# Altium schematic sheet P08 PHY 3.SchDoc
size 420 x 297 mm
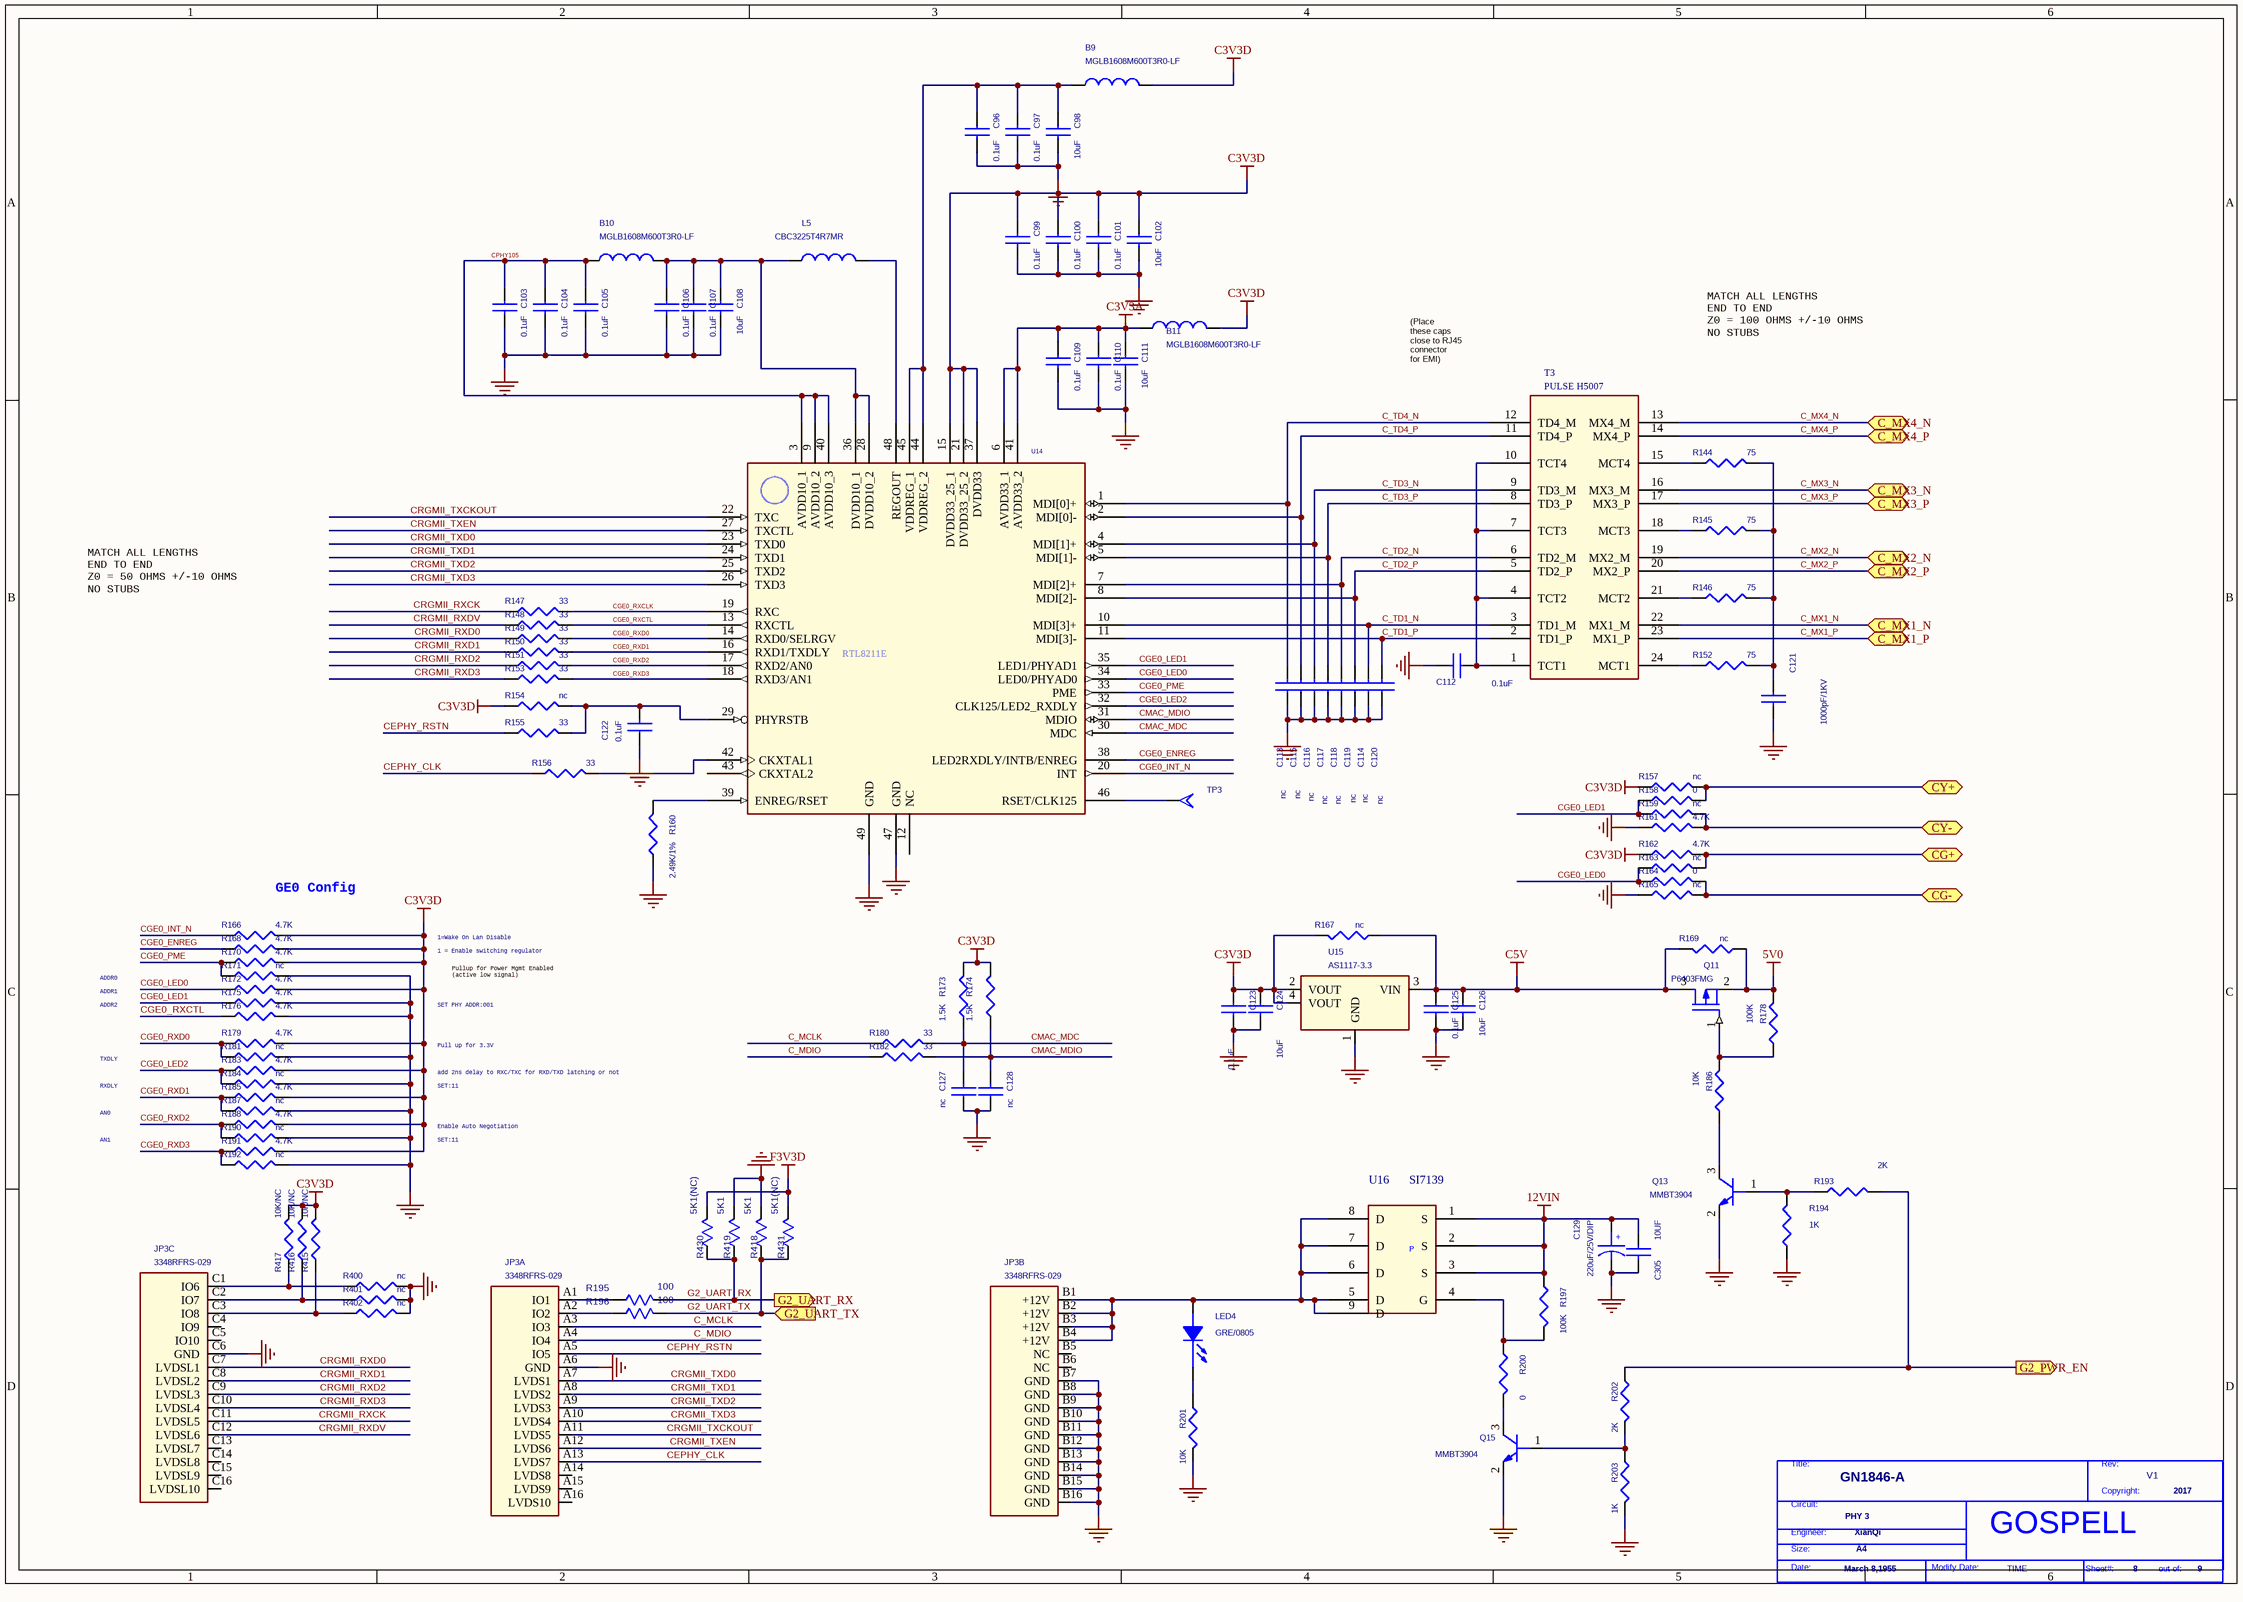
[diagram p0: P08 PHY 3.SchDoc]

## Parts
*  Doc: PHY 3  Page Count: 9  Page Number: 8  Page Create Date: March 8,1955  Page Size: A4  RevCode: V1  Title: GN1846-A  Copyright: 2017  Engineer: XianQi  Page Modify Date: TIME  (hidden comment: GOSPELL)  (graphical)
B9  MGLB1608M600T3R0-LF  [L0603]
B10  MGLB1608M600T3R0-LF  [L0603]
B11  MGLB1608M600T3R0-LF  [L0603]
C96  0.1uF  [0402C]
C97  0.1uF  [0402C]
C98  10uF  [C0603]
C99  0.1uF  [0402C]
C100  0.1uF  [0402C]
C101  0.1uF  [0402C]
C102  10uF  [C0603]
C103  0.1uF  [0402C]
C104  0.1uF  [0402C]
C105  0.1uF  [0402C]
C106  0.1uF  [0402C]
C107  0.1uF  [0402C]
C108  10uF  [C0603]
C109  0.1uF  [0402C]
C110  0.1uF  [0402C]
C111  10uF  [C0603]
C112  0.1uF  [0402C]
C113  nc  [0402C]
C114  nc  [0402C]
C115  nc  [0402C]
C116  nc  [0402C]
C117  nc  [0402C]
C118  nc  [0402C]
C119  nc  [0402C]
C120  nc  [0402C]
C121  1000pF/1KV  [C1206]
C122  0.1uF  [0402C]
C123  0.1uF  [0402C]
C124  10uF  [C0603]
C125  0.1uF  [0402C]
C126  10uF  [C0603]
C127  nc  [0402C]
C128  nc  [0402C]
C129  220uF/25V/DIP  [CE8X3.5]
C305  10UF  [C1206]
JP3  3348RFRS-029  [3348RFRS-029]  (parts A,B,C of 3)
L5  CBC3225T4R7MR  [FB0805]
LED4  GRE/0805  [LED0805]
Q11  P6403FMG  [SOT23]
Q13  MMBT3904  [SOT23]
Q15  MMBT3904  [SOT23]
R144  75  [0402R]
R145  75  [0402R]
R146  75  [0402R]
R147  33  [0402R]
R148  33  [0402R]
R149  33  [0402R]
R150  33  [0402R]
R151  33  [0402R]
R152  75  [0402R]
R153  33  [0402R]
R154  nc  [0402R]
R155  33  [0402R]
R156  33  [0402R]
R157  nc  [0402R]
R158  0  [0402R]
R159  nc  [0402R]
R160  2.49K/1%  [0402R]
R161  4.7K  [0402R]
R162  4.7K  [0402R]
R163  nc  [0402R]
R164  0  [0402R]
R165  nc  [0402R]
R166  4.7K  [0402R]
R167  nc  [R0603]
R168  4.7K  [0402R]
R169  nc  [R0603]
R170  4.7K  [0402R]
R171  nc  [0402R]
R172  4.7K  [0402R]
R173  1.5K  [0402R]
R174  1.5K  [0402R]
R175  4.7K  [0402R]
R176  4.7K  [0402R]
R178  100K  [0402R]
R179  4.7K  [0402R]
R180  33  [0402R]
R181  nc  [0402R]
R182  33  [0402R]
R183  4.7K  [0402R]
R184  nc  [0402R]
R185  4.7K  [0402R]
R186  10K  [0402R]
R187  nc  [0402R]
R188  4.7K  [0402R]
R190  nc  [0402R]
R191  4.7K  [0402R]
R192  nc  [0402R]
R193  2K  [0402R]
R194  1K  [0402R]
R195  100  [0402R]
R196  100  [0402R]
R197  100K  [R0603]
R200  0  [0402R]
R201  10K  [0402R]
R202  2K  [0402R]
R203  1K  [0402R]
R400  nc  [0402R]
R401  nc  [0402R]
R402  nc  [0402R]
R415  10K/NC  [0402R]
R416  10K/NC  [0402R]
R417  10K/NC  [0402R]
R418  5K1  [0402R]
R419  5K1  [0402R]
R430  5K1(NC)  [0402R]
R431  5K1(NC)  [0402R]
T3  PULSE H5007  [H5007-H]
TP3  T POINT A  [TP_G]  (value not drawn)
U14  RTL8211D  [QFN-48P-RTL8211]  (value not drawn)
U15  AS1117-3.3  [SOT223]
U16  SI7139  [PowerPAKSO8]

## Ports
C_MX1_N (bidir), C_MX1_P (bidir), C_MX2_N (bidir), C_MX2_P (bidir), C_MX3_N (bidir), C_MX3_P (bidir), C_MX4_N (bidir), C_MX4_P (bidir), CG+ (bidir), CG- (bidir), CY+ (bidir), CY- (bidir), G2_PWR_EN (out), G2_UART_RX (out), G2_UART_TX (in)

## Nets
5V0: Q11.2(SOURCE) R169.2 R178.1
12VIN: C129.1 C305.1 R197.2 U16.1(S) U16.2(S) U16.3(S)
C3V3A: B11.1 C109.1 C110.1 C111.1 U14.6(AVDD33_1) U14.41(AVDD33_2)
C3V3D: B9.2 B11.2 C99.1 C100.1 C101.1 C102.1 C123.1 C124.1 R154.1 R157.1 R162.1 R166.2 R167.1 R168.2 R170.2 R172.2 R173.2 R174.2 R179.2 R183.2 R185.2 R188.2 R191.2 R415.2 R416.2 R417.2 U14.15(DVDD33_25_1) U14.21(DVDD33_25_2) U14.37(DVDD33) U15.2(VOUT) U15.4(VOUT)
C5V: C125.1 C126.1 Q11.3(DRAIN) R167.2 R169.1 U15.3(VIN)
F3V3D: R430.2(B) R431.2(B)
GND: C96.2 C97.2 C98.2 C99.2 C100.2 C101.2 C102.2 C103.2 C104.2 C105.2 C106.2 C107.2 C108.2 C109.2 C110.2 C111.2 C112.2 C113.1 C114.1 C115.1 C116.1 C117.1 C118.1 C119.1 C120.1 C121.2 C122.1 C123.2 C124.2 C125.2 C126.2 C127.1 C128.1 C129.2 C305.2 JP3.A6(GND) JP3.B7(GND) JP3.B8(GND) JP3.B9(GND) JP3.B10(GND) JP3.B11(GND) JP3.B12(GND) JP3.B13(GND) JP3.B14(GND) JP3.B15(GND) JP3.B16(GND) JP3.C6(GND) Q13.2(EMITTER) Q15.2(EMITTER) R160.1 R161.1 R165.1 R171.2 R175.2 R176.2 R181.2 R184.2 R187.2 R190.2 R192.2 R194.1 R201.1 R203.1 R400.2 R401.2 R402.2 R418.2(B) R419.2(B) U14.47(GND) U14.49(GND) U15.1(GND)
C_MCLK: JP3.A3(IO3) R180.1
C_MDIO: JP3.A4(IO4) R182.1
C_MX1_N: T3.22(MX1_M) ; port C_MX1_N
C_MX1_P: T3.23(MX1_P) ; port C_MX1_P
C_MX2_N: T3.19(MX2_M) ; port C_MX2_N
C_MX2_P: T3.20(MX2_P) ; port C_MX2_P
C_MX3_N: T3.16(MX3_M) ; port C_MX3_N
C_MX3_P: T3.17(MX3_P) ; port C_MX3_P
C_MX4_N: T3.13(MX4_M) ; port C_MX4_N
C_MX4_P: T3.14(MX4_P) ; port C_MX4_P
C_TD1_N: C114.2 T3.3(TD1_M) U14.10(MDI[3]+)
C_TD1_P: C120.2 T3.2(TD1_P) U14.11(MDI[3]-)
C_TD2_N: C118.2 T3.6(TD2_M) U14.7(MDI[2]+)
C_TD2_P: C119.2 T3.5(TD2_P) U14.8(MDI[2]-)
C_TD3_N: C116.2 T3.9(TD3_M) U14.4(MDI[1]+)
C_TD3_P: C117.2 T3.8(TD3_P) U14.5(MDI[1]-)
C_TD4_N: C113.2 T3.12(TD4_M) U14.1(MDI[0]+)
C_TD4_P: C115.2 T3.11(TD4_P) U14.2(MDI[0]-)
CEPHY_CLK: JP3.A13(LVDS7) R156.1
CEPHY_RSTN: JP3.A5(IO5) R155.1
CG+: R162.2 R163.2 ; port CG+
CG-: R164.2 R165.2 ; port CG-
CGE0_ENREG: R168.1 U14.38(LED2RXDLY/INTB/ENREG)
CGE0_INT_N: R166.1 U14.20(INT)
CGE0_LED0: R163.1 R164.1 R172.1 U14.34(LED0/PHYAD0)
CGE0_LED1: R158.1 R159.1 R175.1 U14.35(LED1/PHYAD1)
CGE0_LED2: R183.1 R184.1 U14.32(CLK125/LED2_RXDLY)
CGE0_PME: R170.1 R171.1 U14.33(PME)
CGE0_RXCLK: R147.2 U14.19(RXC)
CGE0_RXCTL: R148.2 R176.1 U14.13(RXCTL)
CGE0_RXD0: R149.2 R179.1 R181.1 U14.14(RXD0/SELRGV)
CGE0_RXD1: R150.2 R185.1 R187.1 U14.16(RXD1/TXDLY)
CGE0_RXD2: R151.2 R188.1 R190.1 U14.17(RXD2/AN0)
CGE0_RXD3: R153.2 R191.1 R192.1 U14.18(RXD3/AN1)
CMAC_MDC: C127.2 R173.1 R180.2 U14.30(MDC)
CMAC_MDIO: C128.2 R174.1 R182.2 U14.31(MDIO)
CPHY105: B10.1 C103.1 C104.1 C105.1 U14.3(AVDD10_1) U14.9(AVDD10_2) U14.40(AVDD10_3)
CRGMII_RXCK: JP3.C11(LVDSL5) R147.1
CRGMII_RXD0: JP3.C7(LVDSL1) R149.1
CRGMII_RXD1: JP3.C8(LVDSL2) R150.1
CRGMII_RXD2: JP3.C9(LVDSL3) R151.1
CRGMII_RXD3: JP3.C10(LVDSL4) R153.1
CRGMII_RXDV: JP3.C12(LVDSL6) R148.1
CRGMII_TXCKOUT: JP3.A11(LVDS5) U14.22(TXC)
CRGMII_TXD0: JP3.A7(LVDS1) U14.23(TXD0)
CRGMII_TXD1: JP3.A8(LVDS2) U14.24(TXD1)
CRGMII_TXD2: JP3.A9(LVDS3) U14.25(TXD2)
CRGMII_TXD3: JP3.A10(LVDS4) U14.26(TXD3)
CRGMII_TXEN: JP3.A12(LVDS6) U14.27(TXCTL)
CY+: R157.2 R158.2 ; port CY+
CY-: R159.2 R161.2 ; port CY-
G2_PWR_EN: R193.2 R202.2 ; port G2_PWR_EN
G2_UART_RX: R195.2(B) R419.1(A) R430.1(A) ; port G2_UART_RX
G2_UART_TX: R196.2(B) R418.1(A) R431.1(A) ; port G2_UART_TX
NetB9_1: B9.1 C96.1 C97.1 C98.1 U14.44(VDDREG_2) U14.45(VDDREG_1)
NetB10_2: B10.2 C106.1 C107.1 C108.1 L5.1 U14.28(DVDD10_2) U14.36(DVDD10_1)
NetC112_1: C112.1 T3.1(TCT1) T3.4(TCT2) T3.7(TCT3) T3.10(TCT4)
NetC121_1: C121.1 R144.2 R145.2 R146.2 R152.2
NetC122_2: C122.2 R154.2 R155.2 U14.29(PHYRSTB)
NetJP3_A1: JP3.A1(IO1) R195.1(A)
NetJP3_A2: JP3.A2(IO2) R196.1(A)
NetJP3_B1: JP3.B1(+12V) JP3.B2(+12V) JP3.B3(+12V) JP3.B4(+12V) LED4.A(ANODE) U16.5(D) U16.6(D) U16.7(D) U16.8(D) U16.9(D)
NetJP3_C1: JP3.C1(IO6) R400.1 R417.1
NetJP3_C2: JP3.C2(IO7) R401.1 R416.1
NetJP3_C3: JP3.C3(IO8) R402.1 R415.1
NetL5_2: L5.2 U14.48(REGOUT)
NetLED4_K: LED4.K(CATHODE) R201.2
NetQ11_1: Q11.1(GATE) R178.2 R186.1
NetQ13_1: Q13.1(BASE) R193.1 R194.2
NetQ13_3: Q13.3(COLLECTOR) R186.2
NetQ15_1: Q15.1(BASE) R202.1 R203.2
NetQ15_3: Q15.3(COLLECTOR) R200.1
NetR144_1: R144.1 T3.15(MCT4)
NetR145_1: R145.1 T3.18(MCT3)
NetR146_1: R146.1 T3.21(MCT2)
NetR152_1: R152.1 T3.24(MCT1)
NetR156_2: R156.2 U14.42(CKXTAL1)
NetR160_2: R160.2 U14.39(ENREG/RSET)
NetR197_1: R197.1 R200.2 U16.4(G)
NetTP3_1: TP3.1(TP) U14.46(RSET/CLK125)

Not connected (* = marked no-connect by the designer): JP3 A14(LVDS8) A15(LVDS9) A16(LVDS10) B5(NC) B6(NC) C4(IO9) C5(IO10) C13(LVDSL7) C14(LVDSL8) C15(LVDSL9) C16(LVDSL10); U14 12(NC) 43(CKXTAL2)

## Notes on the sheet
- (Place
  these caps
  close to RJ45
  connector
  for EMI)
- MATCH ALL LENGTHS
  END TO END
  Z0 = 100 OHMS +/-10 OHMS
  NO STUBS
- MATCH ALL LENGTHS
  END TO END
  Z0 = 50 OHMS +/-10 OHMS
  NO STUBS
- GE0 Config
- 1=Wake On Lan Disable
- ADDR0
- ADDR1
- 1 = Enable switching regulator
- Pullup for Power Mgmt Enabled
  (active low signal)
- ADDR2
- TXDLY
- SET PHY ADDR:001
- Pull up for 3.3V
- add 2ns delay to RXC/TXC for RXD/TXD latching or not
- AN0
- RXDLY
- Enable Auto Negotiation
- SET:11
- AN1

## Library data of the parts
B9-B11 L5 = CHOKE TORROID_0
C96-C128 = CAP NP_Dup1
C129 = CAP POL
C305 = CAP NP
LED4 = LED_0
Q11 = MOSFET P_0
Q13 Q15 = 2N3904
R144-R166 R168 R170-R176 R179-R185 R187 R188 R190-R192 R197 R200-R203 R400-R402 R415-R417 = R_Dup1
R167 R169 R178 R186 R193 R194 = R
R195 R196 R418 R419 R430 R431 = R_1: PARTS: 1; OriginalSymbolOrigin: (10,20); PINSWAP: (A,B); DEVICE: RK73H1JTTD7502F; PKG_TYPE: SR0603; LEVEL: STD; %208%%161%%192%%224%%195%%251%%179%%198%: 片式厚膜电阻器; COMPONENT_HIGH_MAX: 0.55MM; %215%%232%%214%%181%%212%%202%%208%%237%%198%%171%%178%%238%: +/-1%; %182%%238%%182%%168%%185%%166%%194%%202%(W): 0.1; %195%%232%%202%%246%: 片式厚膜电阻器-0.1W-75000OHM-+/-1%-0603; CODE: 7091238
T3 = PULSE H5007_0
U14 = RTL8211D_1
U15 = AS1117-X_2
